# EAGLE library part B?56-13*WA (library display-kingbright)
14.22mm (0.56INCH) THREE DIGIT NUMERIC DISPLAY Source: http://www.kingbright.com .. BA56-11EWA(Ver1189474895.pdf
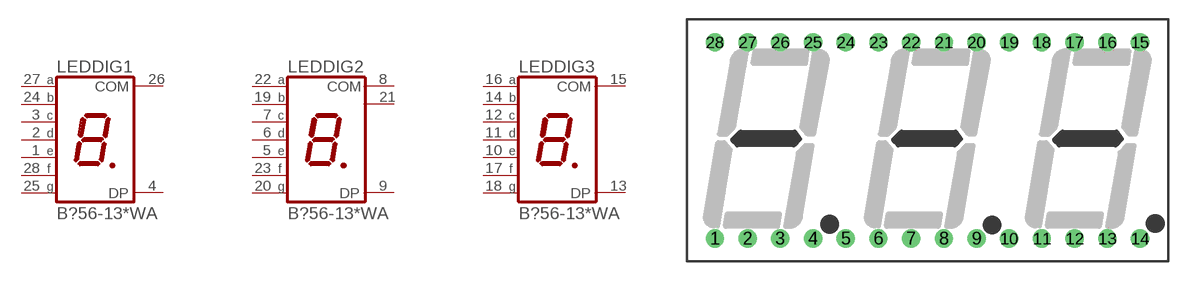
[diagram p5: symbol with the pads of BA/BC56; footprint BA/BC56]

Designator prefix LED; gates DIG1=7SEG-LED-COM1 DIG2=7SEG-LED-COM2 DIG3=7SEG-LED-COM1

## BA56-13EWA (OC_FARNELL: unknown; OC_NEWARK: unknown), BA56-13GWA (OC_FARNELL: unknown; OC_NEWARK: unknown), BA56-13SRWA (OC_FARNELL: unknown; OC_NEWARK: unknown), BA56-13YWA (OC_FARNELL: unknown; OC_NEWARK: unknown)  [BA/BC56]
1  DIG1:E  pas
2  DIG1:D  pas
3  DIG1:C  pas
4  DIG1:DP  pas
5  DIG2:E  pas
6  DIG2:D  pas
7  DIG2:C  pas
8  DIG2:COM  pas
9  DIG2:DP  pas
10  DIG3:E  pas
11  DIG3:D  pas
12  DIG3:C  pas
13  DIG3:DP  pas
14  DIG3:B  pas
15  DIG3:COM  pas
16  DIG3:A  pas
17  DIG3:F  pas
18  DIG3:G  pas
19  DIG2:B  pas
20  DIG2:G  pas
21  DIG2:COM  pas
22  DIG2:A  pas
23  DIG2:F  pas
24  DIG1:B  pas
25  DIG1:G  pas
26  DIG1:COM  pas
27  DIG1:A  pas
28  DIG1:F  pas

## BC56-13EWA (OC_FARNELL: unknown; OC_NEWARK: unknown), BC56-13GWA (OC_FARNELL: unknown; OC_NEWARK: unknown), BC56-13SRWA (OC_FARNELL: unknown; OC_NEWARK: unknown), BC56-13YWA (OC_FARNELL: unknown; OC_NEWARK: unknown)  [BA/BC56]
Pads as for BA/BC56

## Footprint BA/BC56 (pad centres in mm)
14.22mm (0.56INCH) THREE DIGIT NUMERIC DISPLAY Source: http://www.kingbright.com .. BA56-11EWA(Ver1189474895.pdf
drill 0.8 pad 1.422 round: 1 -16.51,-7.62; 2 -13.97,-7.62; 3 -11.43,-7.62; 4 -8.89,-7.62; 5 -6.35,-7.62; 6 -3.81,-7.62; 7 -1.27,-7.62; 8 1.27,-7.62; 9 3.81,-7.62; 10 6.35,-7.62; 11 8.89,-7.62; 12 11.43,-7.62; 13 13.97,-7.62; 14 16.51,-7.62; 15 16.51,7.62; 16 13.97,7.62; 17 11.43,7.62; 18 8.89,7.62; 19 6.35,7.62; 20 3.81,7.62; 21 1.27,7.62; 22 -1.27,7.62; 23 -3.81,7.62; 24 -6.35,7.62; 25 -8.89,7.62; 26 -11.43,7.62; 27 -13.97,7.62; 28 -16.51,7.62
